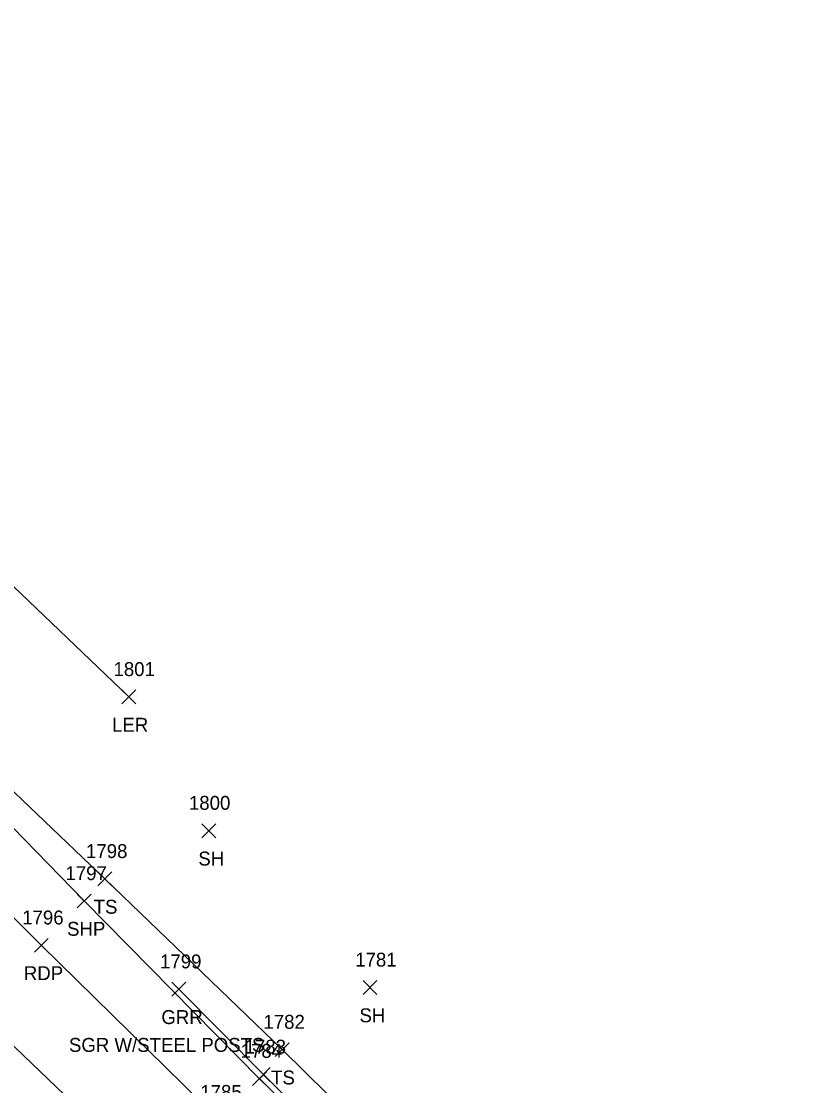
# Model space of a CAD drawing. Extents: x 1647574 to 1652703, y 212895 to 228670.
# Drawn here: x 1648557.9 to 1648670.8, y 227614.7 to 227767.7 of the extents above; entities that cross this region are included whole.
import ezdxf

# ---------------------------------------------------------------- set-up
doc = ezdxf.new("R2010")
doc.units = 0
for name, color, linetype in [('L_A', 7, 'Continuous'), ('L_I', 7, 'Continuous'), ('L_TIC', 7, 'Continuous'), ('LARO', 7, 'Continuous'), ('LELB', 7, 'Continuous'), ('P_A', 7, 'Continuous'), ('P_I', 7, 'Continuous'), ('P_TIC', 7, 'Continuous'), ('PET', 7, 'Continuous'), ('PRC', 7, 'Continuous'), ('PSP', 7, 'Continuous'), ('R_A', 7, 'Continuous'), ('R_C', 7, 'Continuous'), ('R_I', 7, 'Continuous'), ('R_TIC', 7, 'Continuous'), ('RGR', 7, 'Continuous')]:
    doc.layers.add(name, color=color, linetype=linetype)

msp = doc.modelspace()

# ---------------------------------------------------------------- linework, layer by layer
at = {"layer": 'L_TIC'}
for points in [[(1648572.31, 227669.61), (1648574.31, 227671.61)], [(1648574.31, 227669.61), (1648572.31, 227671.61)], [(1648583.8, 227650.39), (1648585.8, 227652.39)], [(1648585.8, 227650.39), (1648583.8, 227652.39)], [(1648568.85, 227643.46), (1648570.85, 227645.46)], [(1648570.85, 227643.46), (1648568.85, 227645.46)], [(1648606.96, 227627.86), (1648608.96, 227629.86)], [(1648608.96, 227627.86), (1648606.96, 227629.86)], [(1648594.33, 227618.93), (1648596.33, 227620.93)], [(1648596.33, 227618.93), (1648594.33, 227620.93)]]:
    msp.add_lwpolyline(points, dxfattribs=at)
at = {"layer": 'LARO'}
msp.add_lwpolyline([(1648573.31, 227670.61), (1648553.35, 227689.67), (1648548.09, 227702.05)], dxfattribs=at)
at = {"layer": 'LELB'}
msp.add_lwpolyline([(1648859.74, 227356.65), (1648840.12, 227378.91), (1648802.29, 227415.99), (1648770.94, 227445.62), (1648740.28, 227477.01), (1648708.8, 227506.87), (1648686.01, 227530.68), (1648664.68, 227552.78), (1648630.72, 227585.09), (1648595.33, 227619.93), (1648569.85, 227644.46), (1648530.91, 227681.62), (1648503.48, 227711.09), (1648474.08, 227742.1), (1648442.94, 227774.58), (1648417.61, 227803.67), (1648387.3, 227839.86), (1648354.19, 227879.71), (1648321.73, 227919.78)], dxfattribs=at)
at = {"layer": 'P_TIC'}
for points in [[(1648565.89, 227640.29), (1648567.89, 227642.29)], [(1648567.89, 227640.29), (1648565.89, 227642.29)], [(1648559.73, 227633.92), (1648561.73, 227635.92)], [(1648561.73, 227633.92), (1648559.73, 227635.92)], [(1648591.06, 227614.76), (1648593.06, 227616.76)], [(1648593.06, 227614.76), (1648591.06, 227616.76)]]:
    msp.add_lwpolyline(points, dxfattribs=at)
at = {"layer": 'PET'}
msp.add_lwpolyline([(1648859.77, 227350.01), (1648834.8, 227373.42), (1648794.62, 227411.18), (1648764.14, 227439.93), (1648732.84, 227469.15), (1648700.82, 227498.96), (1648676.82, 227521.55), (1648654.81, 227542.65), (1648622.51, 227574.49), (1648586.27, 227609.85), (1648560.73, 227634.92), (1648521.71, 227673.76), (1648494.06, 227702.04), (1648464.63, 227733.46), (1648434.45, 227766.66), (1648408.12, 227796.3), (1648377.39, 227832.24), (1648343.92, 227872.68), (1648312.18, 227912.42)], dxfattribs=at)
at = {"layer": 'PRC'}
msp.add_lwpolyline([(1648838.07, 227353.54), (1648807.35, 227381.57), (1648786.43, 227402.05), (1648755.91, 227430.19), (1648724.74, 227459.82), (1648692.84, 227489.5), (1648667.2, 227513.57), (1648644.8, 227535.1), (1648615.58, 227563.67), (1648577.2, 227600.82), (1648552.11, 227624.84), (1648512.09, 227665.31), (1648484.94, 227693.32), (1648454.59, 227725.67), (1648425.77, 227757.32), (1648398.45, 227788.16), (1648367.06, 227824.4), (1648333.96, 227865.19)], dxfattribs=at)
at = {"layer": 'PSP'}
msp.add_lwpolyline([(1648862.79, 227349.77), (1648858.81, 227353.71), (1648837.2, 227376.43), (1648798.17, 227413.97), (1648737.5, 227474.33), (1648707.27, 227504.55), (1648683.25, 227528.38), (1648680.78, 227530.89), (1648661.55, 227548.7), (1648627.48, 227581.41), (1648592.06, 227615.76), (1648566.89, 227641.29), (1648529.07, 227680.17), (1648501.07, 227708.87), (1648471.98, 227739.97), (1648441.35, 227773.22), (1648415.73, 227802.3), (1648385.43, 227838.08), (1648352.03, 227878.52), (1648319.68, 227918.25)], dxfattribs=at)
at = {"layer": 'R_TIC'}
for points in [[(1648579.49, 227627.61), (1648581.49, 227629.61)], [(1648581.49, 227627.61), (1648579.49, 227629.61)], [(1648591.63, 227615.36), (1648593.63, 227617.36)], [(1648593.63, 227615.36), (1648591.63, 227617.36)]]:
    msp.add_lwpolyline(points, dxfattribs=at)
at = {"layer": 'RGR'}
msp.add_lwpolyline([(1648858.35, 227355.78), (1648837.72, 227376.91), (1648798.67, 227414.48), (1648769.05, 227444.38), (1648738.03, 227474.66), (1648707.59, 227505.32), (1648682.61, 227530.03), (1648661.9, 227549.13), (1648627.6, 227581.64), (1648592.63, 227616.36), (1648580.49, 227628.61)], dxfattribs=at)

# ---------------------------------------------------------------- texts
at = {"layer": 'L_A'}
for s, p in [('LER', (1648570.89, 227665.61)), ('SH', (1648583.29, 227646.39)), ('TS', (1648568.25, 227639.46)), ('SH', (1648606.44, 227623.86)), ('TS', (1648593.74, 227614.93))]:
    msp.add_text(s, height=2, dxfattribs=at).set_placement(p)
at = {"layer": 'L_I'}
for s, p in [('1801', (1648571.1, 227673.61)), ('1800', (1648581.94, 227654.39)), ('1798', (1648567.15, 227647.46)), ('1781', (1648605.83, 227631.86)), ('1782', (1648592.64, 227622.93))]:
    msp.add_text(s, height=2, dxfattribs=at).set_placement(p)
at = {"layer": 'P_A'}
for s, p in [('SHP', (1648564.43, 227636.29)), ('RDP', (1648558.22, 227629.92))]:
    msp.add_text(s, height=2, dxfattribs=at).set_placement(p)
at = {"layer": 'P_I'}
for s, p in [('1797', (1648564.2, 227644.29)), ('1796', (1648557.98, 227637.92)), ('1784', (1648589.37, 227618.76)), ('1785', (1648583.57, 227612.85))]:
    msp.add_text(s, height=2, dxfattribs=at).set_placement(p)
at = {"layer": 'R_A'}
msp.add_text('GRR', height=2, dxfattribs=at).set_placement((1648577.98, 227623.61))
at = {"layer": 'R_C'}
msp.add_text('SGR W/STEEL POSTS', height=2, dxfattribs=at).set_placement((1648564.7, 227619.61))
at = {"layer": 'R_I'}
for s, p in [('1799', (1648577.79, 227631.61)), ('1783', (1648589.94, 227619.36))]:
    msp.add_text(s, height=2, dxfattribs=at).set_placement(p)

doc.saveas('drawing.dxf')
